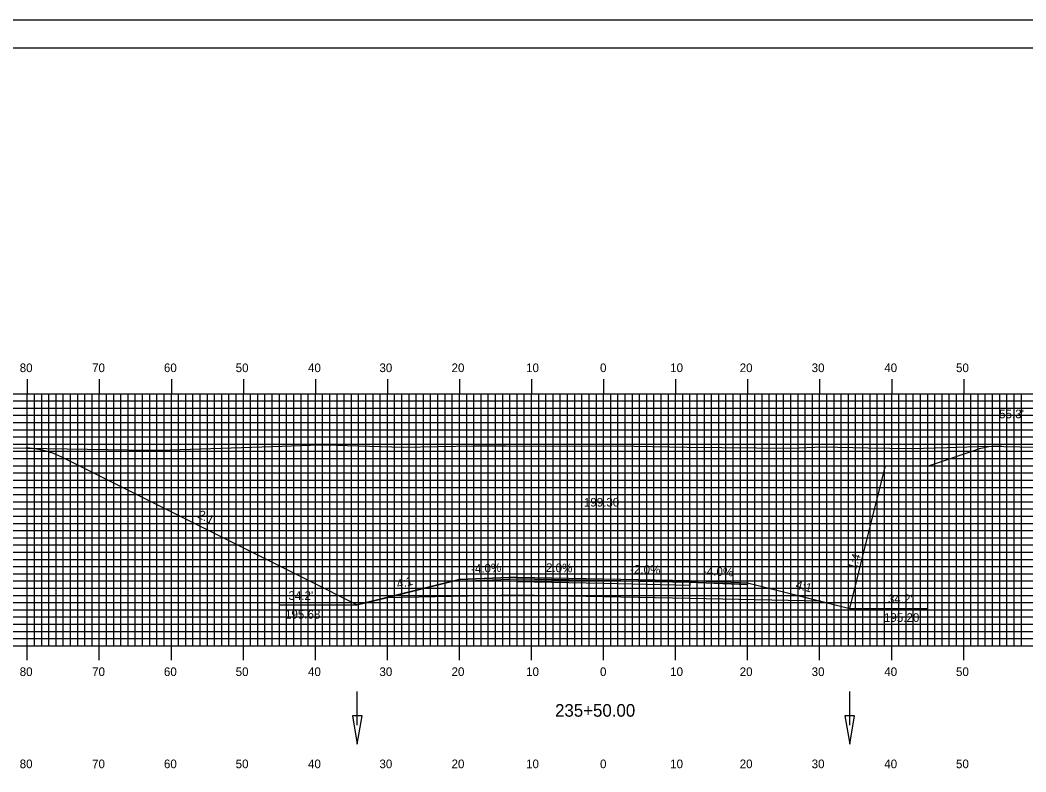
# Model space of a CAD drawing. Extents: x 1800355 to 1800699, y 442591 to 442811.
# Drawn here: x 1800440 to 1800579.7, y 442706.2 to 442810.5 of the extents above; entities that cross this region are included whole.
import ezdxf

# ---------------------------------------------------------------- set-up
doc = ezdxf.new("R2010")
doc.units = 0
for name, color, linetype in [('ANNOTATION', 7, 'Continuous'), ('BORDER', 7, 'Continuous'), ('D_Drainage_Ditch_Line', 7, 'Continuous'), ('D_Roadway_Centerline', 7, 'Continuous'), ('D_Roadway_Centerline_Text', 7, 'Continuous'), ('D_Roadway_Edge_Shoulder', 7, 'Continuous'), ('D_Roadway_Edge_TW', 7, 'Continuous'), ('D_Roadway_Pavement', 7, 'Continuous'), ('D_Roadway_SlopeLines', 7, 'Continuous'), ('D_Roadway_SubGrade', 7, 'Continuous'), ('D_Text_Standard', 7, 'Continuous'), ('H_V ANNOTATION', 7, 'Continuous'), ('MAJOR', 7, 'Continuous'), ('MINOR', 7, 'Continuous'), ('PDRAIN', 7, 'Continuous'), ('PLOT BOUNDARY', 7, 'Continuous'), ('S_Roadway_Centerline', 7, 'Continuous')]:
    doc.layers.add(name, color=color, linetype=linetype)

msp = doc.modelspace()

# ---------------------------------------------------------------- linework, layer by layer
at = {"layer": 'ANNOTATION'}
msp.add_line((1800555.21, 442728.86), (1800557.73, 442738.94), dxfattribs=at)
at = {"layer": 'BORDER'}
msp.add_lwpolyline([(1800371.44, 442596.67), (1800691.44, 442596.67), (1800691.44, 442806.67), (1800371.44, 442806.67)], close=True, dxfattribs=at)
at = {"layer": 'D_Drainage_Ditch_Line'}
for p, q in [((1800486.86, 442712.63), (1800486.86, 442717.33)), ((1800555.21, 442712.63), (1800555.21, 442717.33))]:
    msp.add_line(p, q, dxfattribs=at)
for points in [[(1800487.52, 442713.94), (1800486.21, 442713.94), (1800486.86, 442710)], [(1800555.87, 442713.94), (1800554.55, 442713.94), (1800555.21, 442710)]]:
    msp.add_lwpolyline(points, close=True, dxfattribs=at)
at = {"layer": 'D_Roadway_Centerline'}
msp.add_lwpolyline([(1800486.86, 442729.34), (1800490.86, 442730.34), (1800501.04, 442732.89), (1800509.04, 442733.21), (1800521.04, 442732.97), (1800533.04, 442732.73), (1800541.04, 442732.41), (1800551.21, 442729.86), (1800555.21, 442728.86)], dxfattribs=at)
at = {"layer": 'D_Roadway_Edge_Shoulder'}
for points in [[(1800509.04, 442733.21), (1800501.04, 442732.89), (1800501.04, 442732.64), (1800509.04, 442732.96)], [(1800533.04, 442732.73), (1800541.04, 442732.41), (1800541.04, 442732.16), (1800533.04, 442732.48)]]:
    msp.add_lwpolyline(points, close=True, dxfattribs=at)
at = {"layer": 'D_Roadway_Edge_TW'}
msp.add_lwpolyline([(1800509.04, 442732.96), (1800509.04, 442733.21), (1800521.04, 442732.97), (1800533.04, 442732.73), (1800533.04, 442732.48), (1800521.04, 442732.72)], close=True, dxfattribs=at)
at = {"layer": 'D_Roadway_Pavement'}
msp.add_lwpolyline([(1800509.04, 442732.54), (1800509.04, 442732.96), (1800521.04, 442732.72), (1800533.04, 442732.48), (1800533.04, 442732.06), (1800521.04, 442732.3)], close=True, dxfattribs=at)
at = {"layer": 'D_Roadway_SlopeLines'}
for p, q in [((1800566.16, 442748.67), (1800572.77, 442750.87)), ((1800483.49, 442731.03), (1800486.86, 442729.34))]:
    msp.add_line(p, q, dxfattribs=at)
for points in [[(1800483.49, 442731.03), (1800445.85, 442749.85), (1800444.6, 442750.4), (1800443.35, 442750.79), (1800442.1, 442751.03), (1800440.85, 442751.11)], [(1800557.73, 442738.94), (1800560.16, 442748.67), (1800566.16, 442748.67)], [(1800501.04, 442732.89), (1800486.86, 442729.34)], [(1800541.04, 442732.41), (1800555.21, 442728.86)]]:
    msp.add_lwpolyline(points, dxfattribs=at)
for centre, radius, start, end in [((1800440.6, 442739.6), 11.51, 71.5651, 88.4924), ((1800575.87, 442741.56), 9.81, 87.3695, 108.4349)]:
    msp.add_arc(centre, radius, start, end, dxfattribs=at)
at = {"layer": 'D_Roadway_SubGrade'}
msp.add_lwpolyline([(1800509.04, 442730.71), (1800490.86, 442730.34), (1800501.04, 442732.89), (1800501.04, 442732.64), (1800509.04, 442732.96), (1800521.04, 442732.72), (1800533.04, 442732.48), (1800541.04, 442732.16), (1800541.04, 442732.41), (1800551.21, 442729.86), (1800533.04, 442730.23), (1800521.04, 442730.47)], close=True, dxfattribs=at)
at = {"layer": 'MAJOR'}
for p, q in [((1800441.04, 442760.67), (1800441.04, 442758.67)), ((1800451.04, 442760.67), (1800451.04, 442758.67)), ((1800461.04, 442760.67), (1800461.04, 442758.67)), ((1800471.04, 442760.67), (1800471.04, 442758.67)), ((1800481.04, 442760.67), (1800481.04, 442758.67)), ((1800491.04, 442760.67), (1800491.04, 442758.67)), ((1800501.04, 442760.67), (1800501.04, 442758.67)), ((1800511.04, 442760.67), (1800511.04, 442758.67)), ((1800521.04, 442760.67), (1800521.04, 442758.67)), ((1800531.04, 442760.67), (1800531.04, 442758.67)), ((1800541.04, 442760.67), (1800541.04, 442758.67)), ((1800551.04, 442760.67), (1800551.04, 442758.67)), ((1800561.04, 442760.67), (1800561.04, 442758.67)), ((1800571.04, 442760.67), (1800571.04, 442758.67)), ((1800381.04, 442758.67), (1800661.04, 442758.67)), ((1800381.04, 442758.67), (1800661.04, 442758.67)), ((1800441.04, 442723.67), (1800441.04, 442758.67)), ((1800451.04, 442723.67), (1800451.04, 442758.67)), ((1800461.04, 442723.67), (1800461.04, 442758.67)), ((1800471.04, 442723.67), (1800471.04, 442758.67)), ((1800481.04, 442723.67), (1800481.04, 442758.67)), ((1800491.04, 442723.67), (1800491.04, 442758.67)), ((1800501.04, 442723.67), (1800501.04, 442758.67)), ((1800511.04, 442723.67), (1800511.04, 442758.67)), ((1800521.04, 442723.67), (1800521.04, 442758.67)), ((1800531.04, 442723.67), (1800531.04, 442758.67)), ((1800541.04, 442723.67), (1800541.04, 442758.67)), ((1800551.04, 442723.67), (1800551.04, 442758.67)), ((1800561.04, 442723.67), (1800561.04, 442758.67)), ((1800571.04, 442723.67), (1800571.04, 442758.67)), ((1800381.04, 442753.67), (1800661.04, 442753.67)), ((1800381.04, 442748.67), (1800661.04, 442748.67)), ((1800381.04, 442743.67), (1800661.04, 442743.67)), ((1800381.04, 442738.67), (1800661.04, 442738.67)), ((1800381.04, 442733.67), (1800661.04, 442733.67)), ((1800381.04, 442728.67), (1800661.04, 442728.67)), ((1800381.04, 442723.67), (1800661.04, 442723.67)), ((1800381.04, 442723.67), (1800661.04, 442723.67)), ((1800441.04, 442721.66), (1800441.04, 442723.67)), ((1800451.04, 442721.66), (1800451.04, 442723.67)), ((1800461.04, 442721.66), (1800461.04, 442723.67)), ((1800471.04, 442721.66), (1800471.04, 442723.67)), ((1800481.04, 442721.66), (1800481.04, 442723.67)), ((1800491.04, 442721.66), (1800491.04, 442723.67)), ((1800501.04, 442721.66), (1800501.04, 442723.67)), ((1800511.04, 442721.66), (1800511.04, 442723.67)), ((1800521.04, 442721.66), (1800521.04, 442723.67)), ((1800531.04, 442721.66), (1800531.04, 442723.67)), ((1800541.04, 442721.66), (1800541.04, 442723.67)), ((1800551.04, 442721.66), (1800551.04, 442723.67)), ((1800561.04, 442721.66), (1800561.04, 442723.67)), ((1800571.04, 442721.66), (1800571.04, 442723.67))]:
    msp.add_line(p, q, dxfattribs=at)
at = {"layer": 'MINOR'}
for p, q in [((1800442.04, 442723.67), (1800442.04, 442758.67)), ((1800443.04, 442723.67), (1800443.04, 442758.67)), ((1800444.04, 442723.67), (1800444.04, 442758.67)), ((1800445.04, 442723.67), (1800445.04, 442758.67)), ((1800446.04, 442723.67), (1800446.04, 442758.67)), ((1800447.04, 442723.67), (1800447.04, 442758.67)), ((1800448.04, 442723.67), (1800448.04, 442758.67)), ((1800449.04, 442723.67), (1800449.04, 442758.67)), ((1800450.04, 442723.67), (1800450.04, 442758.67)), ((1800452.04, 442723.67), (1800452.04, 442758.67)), ((1800453.04, 442723.67), (1800453.04, 442758.67)), ((1800454.04, 442723.67), (1800454.04, 442758.67)), ((1800455.04, 442723.67), (1800455.04, 442758.67)), ((1800456.04, 442723.67), (1800456.04, 442758.67)), ((1800457.04, 442723.67), (1800457.04, 442758.67)), ((1800458.04, 442723.67), (1800458.04, 442758.67)), ((1800459.04, 442723.67), (1800459.04, 442758.67)), ((1800460.04, 442723.67), (1800460.04, 442758.67)), ((1800462.04, 442723.67), (1800462.04, 442758.67)), ((1800463.04, 442723.67), (1800463.04, 442758.67)), ((1800464.04, 442723.67), (1800464.04, 442758.67)), ((1800465.04, 442723.67), (1800465.04, 442758.67)), ((1800466.04, 442723.67), (1800466.04, 442758.67)), ((1800467.04, 442723.67), (1800467.04, 442758.67)), ((1800468.04, 442723.67), (1800468.04, 442758.67)), ((1800469.04, 442723.67), (1800469.04, 442758.67)), ((1800470.04, 442723.67), (1800470.04, 442758.67)), ((1800472.04, 442723.67), (1800472.04, 442758.67)), ((1800473.04, 442723.67), (1800473.04, 442758.67)), ((1800474.04, 442723.67), (1800474.04, 442758.67)), ((1800475.04, 442723.67), (1800475.04, 442758.67)), ((1800476.04, 442723.67), (1800476.04, 442758.67)), ((1800477.04, 442723.67), (1800477.04, 442758.67)), ((1800478.04, 442723.67), (1800478.04, 442758.67)), ((1800479.04, 442723.67), (1800479.04, 442758.67)), ((1800480.04, 442723.67), (1800480.04, 442758.67)), ((1800482.04, 442723.67), (1800482.04, 442758.67)), ((1800483.04, 442723.67), (1800483.04, 442758.67)), ((1800484.04, 442723.67), (1800484.04, 442758.67)), ((1800485.04, 442723.67), (1800485.04, 442758.67)), ((1800486.04, 442723.67), (1800486.04, 442758.67)), ((1800487.04, 442723.67), (1800487.04, 442758.67)), ((1800488.04, 442723.67), (1800488.04, 442758.67)), ((1800489.04, 442723.67), (1800489.04, 442758.67)), ((1800490.04, 442723.67), (1800490.04, 442758.67)), ((1800492.04, 442723.67), (1800492.04, 442758.67)), ((1800493.04, 442723.67), (1800493.04, 442758.67)), ((1800494.04, 442723.67), (1800494.04, 442758.67)), ((1800495.04, 442723.67), (1800495.04, 442758.67)), ((1800496.04, 442723.67), (1800496.04, 442758.67)), ((1800497.04, 442723.67), (1800497.04, 442758.67)), ((1800498.04, 442723.67), (1800498.04, 442758.67)), ((1800499.04, 442723.67), (1800499.04, 442758.67)), ((1800500.04, 442723.67), (1800500.04, 442758.67)), ((1800502.04, 442723.67), (1800502.04, 442758.67)), ((1800503.04, 442723.67), (1800503.04, 442758.67)), ((1800504.04, 442723.67), (1800504.04, 442758.67)), ((1800505.04, 442723.67), (1800505.04, 442758.67)), ((1800506.04, 442723.67), (1800506.04, 442758.67)), ((1800507.04, 442723.67), (1800507.04, 442758.67)), ((1800508.04, 442723.67), (1800508.04, 442758.67)), ((1800509.04, 442723.67), (1800509.04, 442758.67)), ((1800510.04, 442723.67), (1800510.04, 442758.67)), ((1800512.04, 442723.67), (1800512.04, 442758.67)), ((1800513.04, 442723.67), (1800513.04, 442758.67)), ((1800514.04, 442723.67), (1800514.04, 442758.67)), ((1800515.04, 442723.67), (1800515.04, 442758.67)), ((1800516.04, 442723.67), (1800516.04, 442758.67)), ((1800517.04, 442723.67), (1800517.04, 442758.67)), ((1800518.04, 442723.67), (1800518.04, 442758.67)), ((1800519.04, 442723.67), (1800519.04, 442758.67)), ((1800520.04, 442723.67), (1800520.04, 442758.67)), ((1800522.04, 442723.67), (1800522.04, 442758.67)), ((1800523.04, 442723.67), (1800523.04, 442758.67)), ((1800524.04, 442723.67), (1800524.04, 442758.67)), ((1800525.04, 442723.67), (1800525.04, 442758.67)), ((1800526.04, 442723.67), (1800526.04, 442758.67)), ((1800527.04, 442723.67), (1800527.04, 442758.67)), ((1800528.04, 442723.67), (1800528.04, 442758.67)), ((1800529.04, 442723.67), (1800529.04, 442758.67)), ((1800530.04, 442723.67), (1800530.04, 442758.67)), ((1800532.04, 442723.67), (1800532.04, 442758.67)), ((1800533.04, 442723.67), (1800533.04, 442758.67)), ((1800534.04, 442723.67), (1800534.04, 442758.67)), ((1800535.04, 442723.67), (1800535.04, 442758.67)), ((1800536.04, 442723.67), (1800536.04, 442758.67)), ((1800537.04, 442723.67), (1800537.04, 442758.67)), ((1800538.04, 442723.67), (1800538.04, 442758.67)), ((1800539.04, 442723.67), (1800539.04, 442758.67)), ((1800540.04, 442723.67), (1800540.04, 442758.67)), ((1800542.04, 442723.67), (1800542.04, 442758.67)), ((1800543.04, 442723.67), (1800543.04, 442758.67)), ((1800544.04, 442723.67), (1800544.04, 442758.67)), ((1800545.04, 442723.67), (1800545.04, 442758.67)), ((1800546.04, 442723.67), (1800546.04, 442758.67)), ((1800547.04, 442723.67), (1800547.04, 442758.67)), ((1800548.04, 442723.67), (1800548.04, 442758.67)), ((1800549.04, 442723.67), (1800549.04, 442758.67)), ((1800550.04, 442723.67), (1800550.04, 442758.67)), ((1800552.04, 442723.67), (1800552.04, 442758.67)), ((1800553.04, 442723.67), (1800553.04, 442758.67)), ((1800554.04, 442723.67), (1800554.04, 442758.67)), ((1800555.04, 442723.67), (1800555.04, 442758.67)), ((1800556.04, 442723.67), (1800556.04, 442758.67)), ((1800557.04, 442723.67), (1800557.04, 442758.67)), ((1800558.04, 442723.67), (1800558.04, 442758.67)), ((1800559.04, 442723.67), (1800559.04, 442758.67)), ((1800560.04, 442723.67), (1800560.04, 442758.67)), ((1800562.04, 442723.67), (1800562.04, 442758.67)), ((1800563.04, 442723.67), (1800563.04, 442758.67)), ((1800564.04, 442723.67), (1800564.04, 442758.67)), ((1800565.04, 442723.67), (1800565.04, 442758.67)), ((1800566.04, 442723.67), (1800566.04, 442758.67)), ((1800567.04, 442723.67), (1800567.04, 442758.67)), ((1800568.04, 442723.67), (1800568.04, 442758.67)), ((1800569.04, 442723.67), (1800569.04, 442758.67)), ((1800570.04, 442723.67), (1800570.04, 442758.67)), ((1800572.04, 442723.67), (1800572.04, 442758.67)), ((1800573.04, 442723.67), (1800573.04, 442758.67)), ((1800574.04, 442723.67), (1800574.04, 442758.67)), ((1800575.04, 442723.67), (1800575.04, 442758.67)), ((1800576.04, 442723.67), (1800576.04, 442758.67)), ((1800577.04, 442723.67), (1800577.04, 442758.67)), ((1800578.04, 442723.67), (1800578.04, 442758.67)), ((1800579.04, 442723.67), (1800579.04, 442758.67)), ((1800381.04, 442757.67), (1800661.04, 442757.67)), ((1800381.04, 442756.67), (1800661.04, 442756.67)), ((1800381.04, 442755.67), (1800661.04, 442755.67)), ((1800381.04, 442754.67), (1800661.04, 442754.67)), ((1800381.04, 442752.67), (1800661.04, 442752.67)), ((1800381.04, 442751.67), (1800661.04, 442751.67)), ((1800381.04, 442750.67), (1800661.04, 442750.67)), ((1800381.04, 442749.67), (1800661.04, 442749.67)), ((1800381.04, 442747.67), (1800661.04, 442747.67)), ((1800381.04, 442746.67), (1800661.04, 442746.67)), ((1800381.04, 442745.67), (1800661.04, 442745.67)), ((1800381.04, 442744.67), (1800661.04, 442744.67)), ((1800381.04, 442742.67), (1800661.04, 442742.67)), ((1800381.04, 442741.67), (1800661.04, 442741.67)), ((1800381.04, 442740.67), (1800661.04, 442740.67)), ((1800381.04, 442739.67), (1800661.04, 442739.67)), ((1800381.04, 442737.67), (1800661.04, 442737.67)), ((1800381.04, 442736.67), (1800661.04, 442736.67)), ((1800381.04, 442735.67), (1800661.04, 442735.67)), ((1800381.04, 442734.67), (1800661.04, 442734.67)), ((1800381.04, 442732.67), (1800661.04, 442732.67)), ((1800381.04, 442731.67), (1800661.04, 442731.67)), ((1800381.04, 442730.67), (1800661.04, 442730.67)), ((1800381.04, 442729.67), (1800661.04, 442729.67)), ((1800381.04, 442727.67), (1800661.04, 442727.67)), ((1800381.04, 442726.67), (1800661.04, 442726.67)), ((1800381.04, 442725.67), (1800661.04, 442725.67)), ((1800381.04, 442724.67), (1800661.04, 442724.67))]:
    msp.add_line(p, q, dxfattribs=at)
at = {"layer": 'PDRAIN'}
for p, q in [((1800476.14, 442729.34), (1800486.86, 442729.34)), ((1800555.21, 442728.86), (1800565.98, 442728.86))]:
    msp.add_line(p, q, dxfattribs=at)
at = {"layer": 'PLOT BOUNDARY'}
msp.add_lwpolyline([(1800355.25, 442590.55), (1800695.25, 442590.55), (1800695.25, 442810.55), (1800355.25, 442810.55)], close=True, dxfattribs=at)
at = {"layer": 'S_Roadway_Centerline'}
msp.add_lwpolyline([(1800438.09, 442751.16), (1800457.88, 442750.84), (1800459.45, 442750.85), (1800475.05, 442751.34), (1800481.7, 442751.55), (1800482.02, 442751.56), (1800482.37, 442751.55), (1800493.21, 442751.25), (1800502.96, 442751.42), (1800505.16, 442751.43), (1800507.51, 442751.42), (1800525.34, 442751.4), (1800532.64, 442751.23), (1800547.07, 442751.09), (1800551.47, 442751.29), (1800557.74, 442751.16), (1800563.86, 442751.08), (1800568.73, 442751.18), (1800574.34, 442751.41), (1800581.1, 442751.24)], dxfattribs=at)

# ---------------------------------------------------------------- texts
at = {"layer": 'ANNOTATION'}
for s, rotation, p in [('2:1', 333.4349, (1800464.6, 442741.51)), ('2:1', 333.4349, (1800464.6, 442741.51)), ('1:4', 70.516, (1800556.04, 442734.1)), ('-4.0%', 2.2906, (1800502.67, 442733.76)), ('2.0%', 358.8542, (1800513.04, 442733.93)), ('-2.0%', 358.8542, (1800524.72, 442733.7)), ('-4.0%', 357.7094, (1800534.83, 442733.46)), ('4:1', 14.0362, (1800492.48, 442731.61)), ('4:1', 345.9638, (1800547.63, 442731.62))]:
    msp.add_text(s, height=1.2, rotation=rotation, dxfattribs=at).set_placement(p)
for s, p in [("34.2'", (1800477.3, 442730.04)), ("34.2'", (1800560.52, 442729.59)), ('195.68', (1800476.82, 442727.44)), ('195.20', (1800559.97, 442726.99))]:
    msp.add_text(s, height=1.2, dxfattribs=at).set_placement(p)
at = {"layer": 'D_Roadway_Centerline'}
for s, p in [('C', (1800521.03, 442732.97)), ('L', (1800521.04, 442732.96))]:
    msp.add_text(s, height=0.0146, dxfattribs=at).set_placement(p)
at = {"layer": 'D_Roadway_Centerline_Text'}
msp.add_text('199.30', height=1.2, dxfattribs=at).set_placement((1800518.31, 442743))
at = {"layer": 'D_Text_Standard'}
msp.add_text("55.3'", height=1.2, dxfattribs=at).set_placement((1800575.96, 442755.26))
at = {"layer": 'H_V ANNOTATION'}
for s, height, p in [('80', 1.2, (1800439.99, 442761.67)), ('70', 1.2, (1800450.04, 442761.67)), ('60', 1.2, (1800460.01, 442761.67)), ('50', 1.2, (1800469.97, 442761.67)), ('40', 1.2, (1800480.01, 442761.67)), ('30', 1.2, (1800489.93, 442761.67)), ('20', 1.2, (1800499.94, 442761.67)), ('10', 1.2, (1800510.29, 442761.67)), ('0', 1.2, (1800520.55, 442761.67)), ('10', 1.2, (1800530.29, 442761.67)), ('20', 1.2, (1800539.94, 442761.67)), ('30', 1.2, (1800549.93, 442761.67)), ('40', 1.2, (1800560.01, 442761.67)), ('50', 1.2, (1800569.97, 442761.67)), ('80', 1.2, (1800439.99, 442719.47)), ('70', 1.2, (1800450.04, 442719.47)), ('60', 1.2, (1800460.01, 442719.47)), ('50', 1.2, (1800469.97, 442719.47)), ('40', 1.2, (1800480.01, 442719.47)), ('30', 1.2, (1800489.93, 442719.47)), ('20', 1.2, (1800499.94, 442719.47)), ('10', 1.2, (1800510.29, 442719.47)), ('0', 1.2, (1800520.55, 442719.47)), ('10', 1.2, (1800530.29, 442719.47)), ('20', 1.2, (1800539.94, 442719.47)), ('30', 1.2, (1800549.93, 442719.47)), ('40', 1.2, (1800560.01, 442719.47)), ('50', 1.2, (1800569.97, 442719.47)), ('235+50.00', 1.75, (1800514.31, 442713.82)), ('80', 1.2, (1800439.99, 442706.67)), ('70', 1.2, (1800450.04, 442706.67)), ('60', 1.2, (1800460.01, 442706.67)), ('50', 1.2, (1800469.97, 442706.67)), ('40', 1.2, (1800480.01, 442706.67)), ('30', 1.2, (1800489.93, 442706.67)), ('20', 1.2, (1800499.94, 442706.67)), ('10', 1.2, (1800510.29, 442706.67)), ('0', 1.2, (1800520.55, 442706.67)), ('10', 1.2, (1800530.29, 442706.67)), ('20', 1.2, (1800539.94, 442706.67)), ('30', 1.2, (1800549.93, 442706.67)), ('40', 1.2, (1800560.01, 442706.67)), ('50', 1.2, (1800569.97, 442706.67))]:
    msp.add_text(s, height=height, dxfattribs=at).set_placement(p)

doc.saveas('drawing.dxf')
